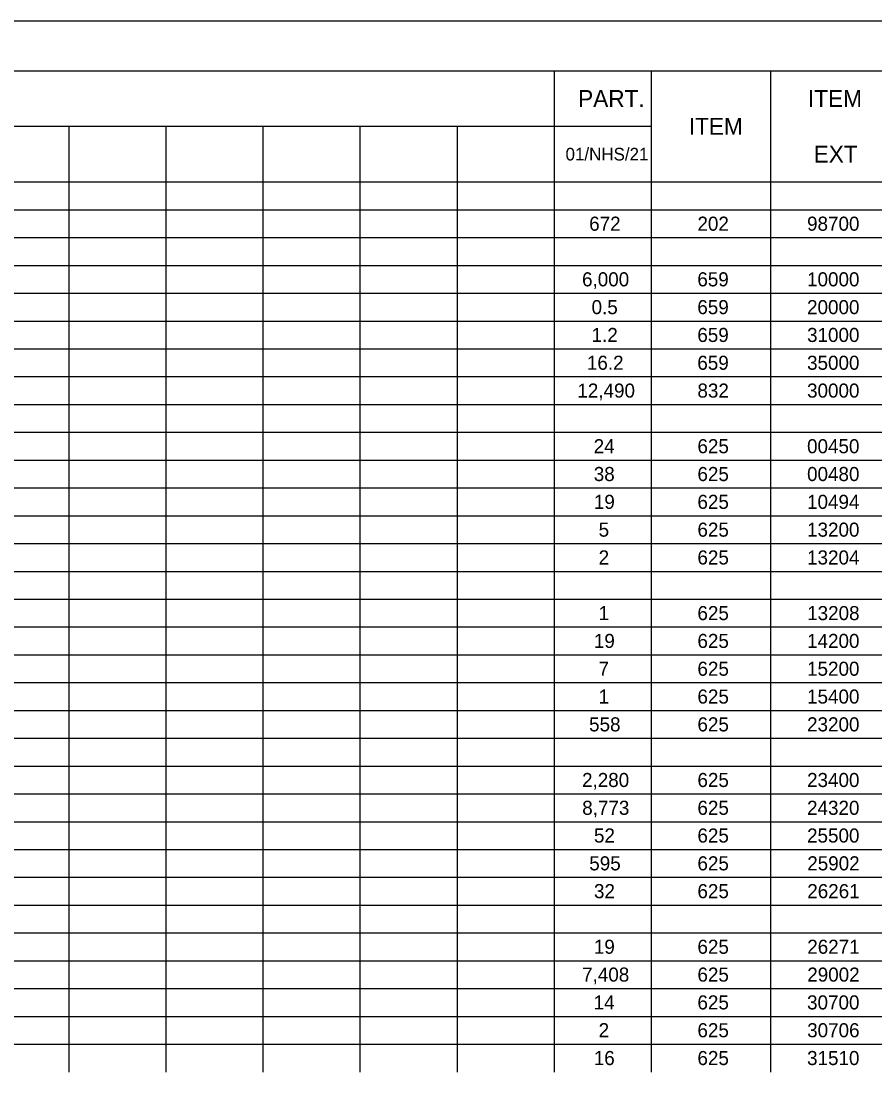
# Model space of a CAD drawing. Extents: x 0 to 34, y 0 to 22.
# Drawn here: x 8.84 to 17.43, y 11.42 to 22 of the extents above; entities that cross this region are included whole.
import ezdxf

# ---------------------------------------------------------------- set-up
doc = ezdxf.new("R2010")
doc.units = 0
for name, color, linetype in [('Default', 7, 'Continuous'), ('SH_Border', 7, 'Continuous'), ('SH_Cut_Line', 7, 'Continuous')]:
    doc.layers.add(name, color=color, linetype=linetype)

msp = doc.modelspace()

# ---------------------------------------------------------------- linework, layer by layer
at = {"layer": 'Default'}
for p, q in [((8.339, 21.5), (13.224, 21.5)), ((13.224, 21.5), (31.083, 21.5)), ((14.201, 21.5), (14.201, 21.22)), ((15.178, 21.5), (15.178, 21.22)), ((16.378, 21.5), (16.378, 21.22)), ((14.201, 21.22), (14.201, 20.94)), ((15.178, 21.22), (15.178, 20.94)), ((16.378, 21.22), (16.378, 20.94)), ((8.339, 20.94), (13.224, 20.94)), ((9.316, 20.94), (9.316, 20.66)), ((10.293, 20.94), (10.293, 20.66)), ((11.27, 20.94), (11.27, 20.66)), ((12.247, 20.94), (12.247, 20.66)), ((13.224, 20.94), (15.178, 20.94)), ((13.224, 20.94), (13.224, 20.66)), ((14.201, 20.94), (14.201, 20.66)), ((15.178, 20.94), (15.178, 20.66)), ((16.378, 20.94), (16.378, 20.66)), ((9.316, 20.66), (9.316, 20.38)), ((10.293, 20.66), (10.293, 20.38)), ((11.27, 20.66), (11.27, 20.38)), ((12.247, 20.66), (12.247, 20.38)), ((13.224, 20.66), (13.224, 20.38)), ((14.201, 20.66), (14.201, 20.38)), ((15.178, 20.66), (15.178, 20.38)), ((16.378, 20.66), (16.378, 20.38)), ((8.339, 20.38), (13.224, 20.38)), ((9.316, 20.38), (9.316, 20.1)), ((10.293, 20.38), (10.293, 20.1)), ((11.27, 20.38), (11.27, 20.1)), ((12.247, 20.38), (12.247, 20.1)), ((13.224, 20.38), (31.083, 20.38)), ((13.224, 20.38), (13.224, 20.1)), ((14.201, 20.38), (14.201, 20.1)), ((15.178, 20.38), (15.178, 20.1)), ((16.378, 20.38), (16.378, 20.1)), ((8.339, 20.1), (13.224, 20.1)), ((9.316, 20.1), (9.316, 18.7)), ((10.293, 20.1), (10.293, 18.7)), ((11.27, 20.1), (11.27, 18.7)), ((12.247, 20.1), (12.247, 18.7)), ((13.224, 20.1), (31.083, 20.1)), ((13.224, 20.1), (13.224, 18.7)), ((14.201, 20.1), (14.201, 18.7)), ((15.178, 20.1), (15.178, 18.7)), ((16.378, 20.1), (16.378, 18.7)), ((8.339, 19.82), (13.224, 19.82)), ((13.224, 19.82), (31.083, 19.82)), ((8.339, 19.54), (13.224, 19.54)), ((13.224, 19.54), (31.083, 19.54)), ((8.339, 19.26), (13.224, 19.26)), ((13.224, 19.26), (31.083, 19.26)), ((8.339, 18.98), (13.224, 18.98)), ((13.224, 18.98), (31.083, 18.98)), ((8.339, 18.7), (13.224, 18.7)), ((9.316, 18.7), (9.316, 18.14)), ((10.293, 18.7), (10.293, 18.14)), ((11.27, 18.7), (11.27, 18.14)), ((12.247, 18.7), (12.247, 18.14)), ((13.224, 18.7), (31.083, 18.7)), ((13.224, 18.7), (13.224, 18.14)), ((14.201, 18.7), (14.201, 18.14)), ((15.178, 18.7), (15.178, 18.14)), ((16.378, 18.7), (16.378, 18.14)), ((8.339, 18.42), (13.224, 18.42)), ((13.224, 18.42), (31.083, 18.42)), ((8.339, 18.14), (13.224, 18.14)), ((9.316, 18.14), (9.316, 17.86)), ((10.293, 18.14), (10.293, 17.86)), ((11.27, 18.14), (11.27, 17.86)), ((12.247, 18.14), (12.247, 17.86)), ((13.224, 18.14), (31.083, 18.14)), ((13.224, 18.14), (13.224, 17.86)), ((14.201, 18.14), (14.201, 17.86)), ((15.178, 18.14), (15.178, 17.86)), ((16.378, 18.14), (16.378, 17.86)), ((8.339, 17.86), (13.224, 17.86)), ((9.316, 17.86), (9.316, 17.58)), ((10.293, 17.86), (10.293, 17.58)), ((11.27, 17.86), (11.27, 17.58)), ((12.247, 17.86), (12.247, 17.58)), ((13.224, 17.86), (31.083, 17.86)), ((13.224, 17.86), (13.224, 17.58)), ((14.201, 17.86), (14.201, 17.58)), ((15.178, 17.86), (15.178, 17.58)), ((16.378, 17.86), (16.378, 17.58)), ((8.339, 17.58), (13.224, 17.58)), ((9.316, 17.58), (9.316, 17.3)), ((10.293, 17.58), (10.293, 17.3)), ((11.27, 17.58), (11.27, 17.3)), ((12.247, 17.58), (12.247, 17.3)), ((13.224, 17.58), (31.083, 17.58)), ((13.224, 17.58), (13.224, 17.3)), ((14.201, 17.58), (14.201, 17.3)), ((15.178, 17.58), (15.178, 17.3)), ((16.378, 17.58), (16.378, 17.3)), ((8.339, 17.3), (13.224, 17.3)), ((9.316, 17.3), (9.316, 17.02)), ((10.293, 17.3), (10.293, 17.02)), ((11.27, 17.3), (11.27, 17.02)), ((12.247, 17.3), (12.247, 17.02)), ((13.224, 17.3), (31.083, 17.3)), ((13.224, 17.3), (13.224, 17.02)), ((14.201, 17.3), (14.201, 17.02)), ((15.178, 17.3), (15.178, 17.02)), ((16.378, 17.3), (16.378, 17.02)), ((8.339, 17.02), (13.224, 17.02)), ((9.316, 17.02), (9.316, 16.74)), ((10.293, 17.02), (10.293, 16.74)), ((11.27, 17.02), (11.27, 16.74)), ((12.247, 17.02), (12.247, 16.74)), ((13.224, 17.02), (31.083, 17.02)), ((13.224, 17.02), (13.224, 16.74)), ((14.201, 17.02), (14.201, 16.74)), ((15.178, 17.02), (15.178, 16.74)), ((16.378, 17.02), (16.378, 16.74)), ((8.339, 16.74), (13.224, 16.74)), ((9.316, 16.74), (9.316, 16.18)), ((10.293, 16.74), (10.293, 16.18)), ((11.27, 16.74), (11.27, 16.18)), ((12.247, 16.74), (12.247, 16.18)), ((13.224, 16.74), (31.083, 16.74)), ((13.224, 16.74), (13.224, 16.18)), ((14.201, 16.74), (14.201, 16.18)), ((15.178, 16.74), (15.178, 16.18)), ((16.378, 16.74), (16.378, 16.18)), ((8.339, 16.46), (13.224, 16.46)), ((13.224, 16.46), (31.083, 16.46)), ((8.339, 16.18), (13.224, 16.18)), ((9.316, 16.18), (9.316, 15.9)), ((10.293, 16.18), (10.293, 15.9)), ((11.27, 16.18), (11.27, 15.9)), ((12.247, 16.18), (12.247, 15.9)), ((13.224, 16.18), (31.083, 16.18)), ((13.224, 16.18), (13.224, 15.9)), ((14.201, 16.18), (14.201, 15.9)), ((15.178, 16.18), (15.178, 15.9)), ((16.378, 16.18), (16.378, 15.9)), ((8.339, 15.9), (13.224, 15.9)), ((9.316, 15.9), (9.316, 15.62)), ((10.293, 15.9), (10.293, 15.62)), ((11.27, 15.9), (11.27, 15.62)), ((12.247, 15.9), (12.247, 15.62)), ((13.224, 15.9), (31.083, 15.9)), ((13.224, 15.9), (13.224, 15.62)), ((14.201, 15.9), (14.201, 15.62)), ((15.178, 15.9), (15.178, 15.62)), ((16.378, 15.9), (16.378, 15.62)), ((8.339, 15.62), (13.224, 15.62)), ((9.316, 15.62), (9.316, 15.34)), ((10.293, 15.62), (10.293, 15.34)), ((11.27, 15.62), (11.27, 15.34)), ((12.247, 15.62), (12.247, 15.34)), ((13.224, 15.62), (31.083, 15.62)), ((13.224, 15.62), (13.224, 15.34)), ((14.201, 15.62), (14.201, 15.34)), ((15.178, 15.62), (15.178, 15.34)), ((16.378, 15.62), (16.378, 15.34)), ((8.339, 15.34), (13.224, 15.34)), ((9.316, 15.34), (9.316, 14.78)), ((10.293, 15.34), (10.293, 14.78)), ((11.27, 15.34), (11.27, 14.78)), ((12.247, 15.34), (12.247, 14.78)), ((13.224, 15.34), (31.083, 15.34)), ((13.224, 15.34), (13.224, 14.78)), ((14.201, 15.34), (14.201, 14.78)), ((15.178, 15.34), (15.178, 14.78)), ((16.378, 15.34), (16.378, 14.78)), ((8.339, 15.06), (13.224, 15.06)), ((13.224, 15.06), (31.083, 15.06)), ((8.339, 14.78), (13.224, 14.78)), ((9.316, 14.78), (9.316, 14.5)), ((10.293, 14.78), (10.293, 14.5)), ((11.27, 14.78), (11.27, 14.5)), ((12.247, 14.78), (12.247, 14.5)), ((13.224, 14.78), (31.083, 14.78)), ((13.224, 14.78), (13.224, 14.5)), ((14.201, 14.78), (14.201, 14.5)), ((15.178, 14.78), (15.178, 14.5)), ((16.378, 14.78), (16.378, 14.5)), ((8.339, 14.5), (13.224, 14.5)), ((9.316, 14.5), (9.316, 14.22)), ((10.293, 14.5), (10.293, 14.22)), ((11.27, 14.5), (11.27, 14.22)), ((12.247, 14.5), (12.247, 14.22)), ((13.224, 14.5), (31.083, 14.5)), ((13.224, 14.5), (13.224, 14.22)), ((14.201, 14.5), (14.201, 14.22)), ((15.178, 14.5), (15.178, 14.22)), ((16.378, 14.5), (16.378, 14.22)), ((8.339, 14.22), (13.224, 14.22)), ((9.316, 14.22), (9.316, 13.94)), ((10.293, 14.22), (10.293, 13.94)), ((11.27, 14.22), (11.27, 13.94)), ((12.247, 14.22), (12.247, 13.94)), ((13.224, 14.22), (31.083, 14.22)), ((13.224, 14.22), (13.224, 13.94)), ((14.201, 14.22), (14.201, 13.94)), ((15.178, 14.22), (15.178, 13.94)), ((16.378, 14.22), (16.378, 13.94)), ((8.339, 13.94), (13.224, 13.94)), ((9.316, 13.94), (9.316, 11.7)), ((10.293, 13.94), (10.293, 11.7)), ((11.27, 13.94), (11.27, 11.7)), ((12.247, 13.94), (12.247, 11.7)), ((13.224, 13.94), (31.083, 13.94)), ((13.224, 13.94), (13.224, 11.7)), ((14.201, 13.94), (14.201, 11.7)), ((15.178, 13.94), (15.178, 11.7)), ((16.378, 13.94), (16.378, 11.7)), ((8.339, 13.66), (13.224, 13.66)), ((13.224, 13.66), (31.083, 13.66)), ((8.339, 13.38), (13.224, 13.38)), ((13.224, 13.38), (31.083, 13.38)), ((8.339, 13.1), (13.224, 13.1)), ((13.224, 13.1), (31.083, 13.1)), ((8.339, 12.82), (13.224, 12.82)), ((13.224, 12.82), (31.083, 12.82)), ((8.339, 12.54), (13.224, 12.54)), ((13.224, 12.54), (31.083, 12.54)), ((8.339, 12.26), (13.224, 12.26)), ((13.224, 12.26), (31.083, 12.26)), ((8.339, 11.98), (13.224, 11.98)), ((13.224, 11.98), (31.083, 11.98)), ((8.339, 11.7), (13.224, 11.7)), ((9.316, 11.7), (9.316, 11.42)), ((10.293, 11.7), (10.293, 11.42)), ((11.27, 11.7), (11.27, 11.42)), ((12.247, 11.7), (12.247, 11.42)), ((13.224, 11.7), (31.083, 11.7)), ((13.224, 11.7), (13.224, 11.42)), ((14.201, 11.7), (14.201, 11.42)), ((15.178, 11.7), (15.178, 11.42)), ((16.378, 11.7), (16.378, 11.42))]:
    msp.add_line(p, q, dxfattribs=at)
at = {"layer": 'SH_Border'}
msp.add_lwpolyline([(1.5, 21.5), (33.5, 21.5), (33.5, 0.5), (1.5, 0.5)], close=True, dxfattribs=at)
at = {"layer": 'SH_Cut_Line'}
msp.add_lwpolyline([(0, 0), (34, 0), (34, 22), (0, 22)], close=True, dxfattribs=at)

# ---------------------------------------------------------------- texts
at = {"layer": 'Default'}
for s, height, p in [('PART.', 0.17, (14.442, 21.135)), ('ITEM', 0.17, (16.754, 21.135)), ('ITEM', 0.17, (15.555, 20.855)), ('EXT', 0.17, (16.812, 20.575)), ('01/NHS/21', 0.1275, (14.315, 20.596)), ('672', 0.1417, (14.553, 19.889)), ('202', 0.1417, (15.642, 19.889)), ('98700', 0.1417, (16.745, 19.889)), ('6,000', 0.1417, (14.481, 19.329)), ('659', 0.1417, (15.641, 19.329)), ('10000', 0.1417, (16.745, 19.329)), ('0.5', 0.1417, (14.577, 19.049)), ('659', 0.1417, (15.641, 19.049)), ('20000', 0.1417, (16.745, 19.049)), ('1.2', 0.1417, (14.577, 18.769)), ('659', 0.1417, (15.641, 18.769)), ('31000', 0.1417, (16.745, 18.769)), ('16.2', 0.1417, (14.53, 18.489)), ('659', 0.1417, (15.641, 18.489)), ('35000', 0.1417, (16.745, 18.489)), ('12,490', 0.1417, (14.434, 18.209)), ('832', 0.1417, (15.642, 18.209)), ('30000', 0.1417, (16.745, 18.209)), ('24', 0.1417, (14.598, 17.649)), ('625', 0.1417, (15.642, 17.649)), ('00450', 0.1417, (16.745, 17.649)), ('38', 0.1417, (14.599, 17.369)), ('625', 0.1417, (15.642, 17.369)), ('00480', 0.1417, (16.745, 17.369)), ('19', 0.1417, (14.6, 17.089)), ('625', 0.1417, (15.642, 17.089)), ('10494', 0.1417, (16.745, 17.089)), ('5', 0.142, (14.648, 16.809)), ('625', 0.1417, (15.642, 16.809)), ('13200', 0.1417, (16.745, 16.809)), ('2', 0.142, (14.648, 16.529)), ('625', 0.1417, (15.642, 16.529)), ('13204', 0.1417, (16.745, 16.529)), ('1', 0.142, (14.648, 15.969)), ('625', 0.1417, (15.642, 15.969)), ('13208', 0.1417, (16.746, 15.969)), ('19', 0.1417, (14.6, 15.689)), ('625', 0.1417, (15.642, 15.689)), ('14200', 0.1417, (16.745, 15.689)), ('625', 0.1417, (15.642, 15.409)), ('15200', 0.1417, (16.745, 15.409)), ('7', 0.142, (14.647, 15.409)), ('1', 0.142, (14.648, 15.129)), ('625', 0.1417, (15.642, 15.129)), ('15400', 0.1417, (16.745, 15.129)), ('558', 0.1417, (14.552, 14.849)), ('625', 0.1417, (15.642, 14.849)), ('23200', 0.1417, (16.745, 14.849)), ('2,280', 0.1417, (14.481, 14.289)), ('625', 0.1417, (15.642, 14.289)), ('23400', 0.1417, (16.745, 14.289)), ('8,773', 0.1417, (14.483, 14.009)), ('625', 0.1417, (15.642, 14.009)), ('24320', 0.1417, (16.745, 14.009)), ('52', 0.1417, (14.601, 13.73)), ('625', 0.1417, (15.642, 13.73)), ('25500', 0.1417, (16.745, 13.73)), ('595', 0.1417, (14.554, 13.45)), ('625', 0.1417, (15.642, 13.45)), ('25902', 0.1417, (16.747, 13.45)), ('32', 0.1417, (14.601, 13.17)), ('625', 0.1417, (15.642, 13.17)), ('26261', 0.1417, (16.747, 13.17)), ('19', 0.1417, (14.6, 12.61)), ('625', 0.1417, (15.642, 12.61)), ('26271', 0.1417, (16.747, 12.61)), ('7,408', 0.1417, (14.482, 12.33)), ('625', 0.1417, (15.642, 12.33)), ('29002', 0.1417, (16.747, 12.33)), ('14', 0.1417, (14.598, 12.05)), ('625', 0.1417, (15.642, 12.05)), ('30700', 0.1417, (16.745, 12.05)), ('2', 0.142, (14.648, 11.77)), ('625', 0.1417, (15.642, 11.77)), ('30706', 0.1417, (16.746, 11.77)), ('16', 0.1417, (14.599, 11.49)), ('625', 0.1417, (15.642, 11.49)), ('31510', 0.1417, (16.745, 11.49))]:
    msp.add_text(s, height=height, dxfattribs=at).set_placement(p)

doc.saveas('drawing.dxf')
